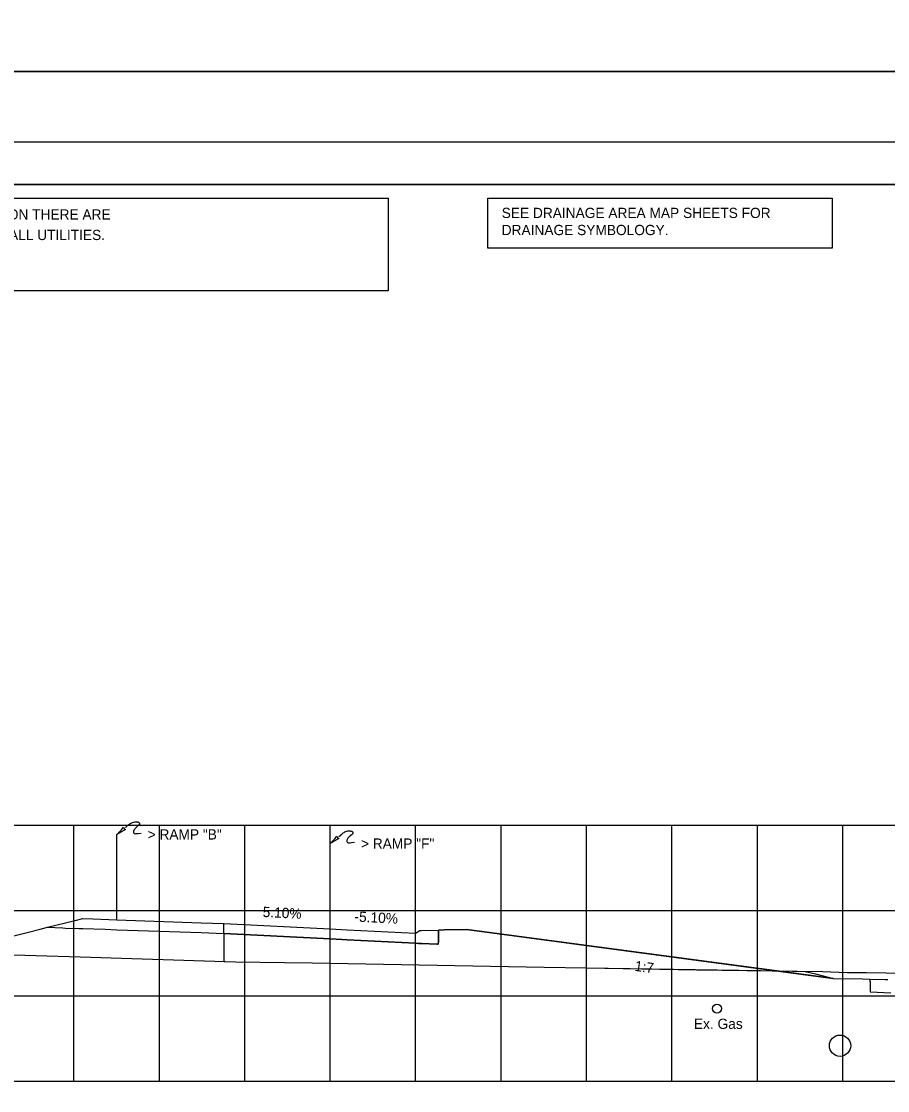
# Model space of a CAD drawing. Extents: x 2148105 to 2149976, y 144169 to 149705.
# Drawn here: x 2148377.2 to 2148478.6, y 144545.8 to 144671 of the extents above; entities that cross this region are included whole.
import ezdxf

# ---------------------------------------------------------------- set-up
doc = ezdxf.new("R2010")
doc.units = 0
for name, color, linetype in [('Bridge M-Header', 7, 'Continuous'), ('Default', 7, 'Continuous'), ('EX_Align', 7, 'Continuous'), ('INR_Tracking', 7, 'Continuous'), ('Ph1-PR-Ramp SF3 Rev-Curb', 7, 'Continuous'), ('PH1a-PR-DividingStrip', 7, 'Continuous'), ('PH1a-PR-ServRd', 7, 'Continuous'), ('PH2-PR-Barrier', 7, 'Continuous'), ('PR-ApproachSlab', 7, 'Continuous'), ('PR-Dividing Strip', 7, 'Continuous'), ('PR-SHLDR-RMP-H', 7, 'Continuous'), ('PR_Align_PI', 7, 'Continuous'), ('PR_Align_Ramp_E', 7, 'Continuous'), ('PR_Align_Ramp_J', 7, 'Continuous'), ('PR_Storm_Channel', 7, 'Continuous'), ('PR_Storm_Conc_Box_PH1B', 7, 'Continuous'), ('PR_Storm_Conc_Pipe', 7, 'Continuous'), ('PR_Storm_Conc_Pipe_PH1B', 7, 'Continuous'), ('PR_Storm_Inlet_CICI_PH1B', 7, 'Continuous'), ('PR_Storm_Junction_Box_PH1A', 7, 'Continuous'), ('PR_Storm_MH', 7, 'Continuous'), ('PR_Storm_Standard_Median_Drain_PH1B', 7, 'Continuous'), ('TopCut', 7, 'Continuous'), ('TOPO_BRIDGE_Pier Cap', 7, 'Continuous')]:
    doc.layers.add(name, color=color, linetype=linetype)

# ---------------------------------------------------------------- blocks, each defined once
blk = doc.blocks.new('POINT_DISPLAY')
at = {"layer": 'Default'}
blk.add_line((0, 0), (0, 0), dxfattribs=at)

msp = doc.modelspace()

# ---------------------------------------------------------------- linework, layer by layer
at = {"layer": 'EX_Align'}
msp.add_lwpolyline([(2148372.17, 144562.92), (2148377.99, 144564.37), (2148379.38, 144564.71), (2148380.24, 144564.93), (2148382.02, 144564.87), (2148382.35, 144564.85), (2148383.89, 144564.8), (2148384.35, 144564.79), (2148386.96, 144564.7), (2148388.36, 144564.65), (2148398.2, 144564.31), (2148400.86, 144564.22)], dxfattribs=at)
at = {"layer": 'INR_Tracking'}
msp.add_lwpolyline([(2148400.86, 144564.22), (2148413.32, 144563.58), (2148413.32, 144563.58), (2148414.66, 144563.51), (2148415.32, 144563.48), (2148415.32, 144563.48), (2148423.32, 144563.07), (2148423.66, 144563.05), (2148423.99, 144563.04), (2148425.84, 144562.94), (2148425.97, 144562.94), (2148425.98, 144563.27), (2148425.99, 144564.61), (2148426.69, 144564.62), (2148429.32, 144564.68), (2148472.18, 144558.95), (2148472.18, 144558.95)], dxfattribs=at)
at = {"layer": 'Ph1-PR-Ramp SF3 Rev-Curb'}
msp.add_circle((2148472.99, 144551.07), 1.25, dxfattribs=at)
at = {"layer": 'PH1a-PR-ServRd'}
msp.add_lwpolyline([(2148570.82, 144441.91), (2148255.82, 144441.91), (2148255.82, 144651.91), (2148570.82, 144651.91)], close=True, dxfattribs=at)
at = {"layer": 'PH2-PR-Barrier'}
msp.add_line((2148413.32, 144564.75), (2148413.32, 144574.75), dxfattribs=at)
for points in [[(2148413.32, 144574.75), (2148413.84, 144575.3), (2148414.1, 144575.6), (2148414.18, 144575.44), (2148414.32, 144575.32), (2148413.32, 144574.75)], [(2148414.33, 144575.56), (2148414.69, 144575.85), (2148414.85, 144575.98), (2148414.94, 144576.05), (2148415.04, 144576.11), (2148415.14, 144576.16), (2148415.26, 144576.19), (2148415.39, 144576.22), (2148415.49, 144576.23), (2148415.57, 144576.23), (2148415.65, 144576.23), (2148415.72, 144576.21), (2148415.78, 144576.2), (2148415.83, 144576.18), (2148415.87, 144576.15), (2148415.91, 144576.12), (2148415.95, 144576.08), (2148415.98, 144576.02), (2148415.97, 144575.96), (2148415.96, 144575.92), (2148415.91, 144575.85), (2148415.72, 144575.69), (2148415.53, 144575.53), (2148415.46, 144575.45), (2148415.39, 144575.38), (2148415.33, 144575.28), (2148415.29, 144575.22), (2148415.25, 144575.13), (2148415.25, 144575.05), (2148415.27, 144574.97), (2148415.31, 144574.9), (2148415.36, 144574.87), (2148415.42, 144574.84), (2148415.53, 144574.83), (2148415.66, 144574.83), (2148415.82, 144574.85), (2148416.15, 144574.89)]]:
    msp.add_lwpolyline(points, dxfattribs=at)
at = {"layer": 'PR-ApproachSlab'}
msp.add_lwpolyline([(2148468.9, 144559.77), (2148470.11, 144559.47), (2148472.18, 144558.95), (2148475.61, 144558.88), (2148476.47, 144558.86), (2148478.26, 144558.83), (2148478.51, 144558.82), (2148478.52, 144558.82), (2148478.52, 144558.82), (2148478.59, 144558.82)], dxfattribs=at)
at = {"layer": 'PR-Dividing Strip'}
msp.add_line((2148388.36, 144565.81), (2148388.36, 144575.81), dxfattribs=at)
for points in [[(2148389.37, 144576.63), (2148389.72, 144576.92), (2148389.88, 144577.05), (2148389.98, 144577.12), (2148390.08, 144577.18), (2148390.18, 144577.22), (2148390.29, 144577.26), (2148390.43, 144577.29), (2148390.52, 144577.3), (2148390.6, 144577.3), (2148390.69, 144577.29), (2148390.76, 144577.28), (2148390.81, 144577.26), (2148390.86, 144577.24), (2148390.91, 144577.22), (2148390.94, 144577.19), (2148390.98, 144577.14), (2148391.01, 144577.09), (2148391.01, 144577.03), (2148391, 144576.99), (2148390.94, 144576.92), (2148390.75, 144576.76), (2148390.57, 144576.59), (2148390.49, 144576.52), (2148390.43, 144576.44), (2148390.36, 144576.35), (2148390.33, 144576.29), (2148390.29, 144576.2), (2148390.28, 144576.12), (2148390.3, 144576.04), (2148390.35, 144575.97), (2148390.39, 144575.93), (2148390.45, 144575.91), (2148390.56, 144575.89), (2148390.7, 144575.9), (2148390.85, 144575.92), (2148391.19, 144575.95)], [(2148388.36, 144575.81), (2148388.87, 144576.36), (2148389.13, 144576.67), (2148389.22, 144576.5), (2148389.36, 144576.39), (2148388.36, 144575.81)]]:
    msp.add_lwpolyline(points, dxfattribs=at)
at = {"layer": 'PR-SHLDR-RMP-H'}
msp.add_lwpolyline([(2148468.9, 144559.77), (2148470.11, 144559.47), (2148472.18, 144558.95), (2148475.61, 144558.88), (2148476.47, 144558.86), (2148476.48, 144558.81), (2148476.48, 144558.53), (2148476.49, 144558.53), (2148476.5, 144558.53), (2148476.52, 144557.84), (2148476.52, 144557.7), (2148476.52, 144557.64), (2148476.53, 144557.37), (2148478.92, 144557.25)], dxfattribs=at)
at = {"layer": 'PR_Align_PI'}
msp.add_lwpolyline([(2148380.24, 144564.93), (2148383.48, 144565.73), (2148384.36, 144565.95), (2148385.53, 144565.91), (2148388.36, 144565.81), (2148398.21, 144565.47), (2148400.86, 144565.38)], dxfattribs=at)
at = {"layer": 'PR_Align_Ramp_E'}
for points in [[(2148219.95, 144905.16), (2148579.95, 144905.16), (2148579.95, 144665.16), (2148219.95, 144665.16)], [(2148219.95, 144665.16), (2148579.95, 144665.16), (2148579.95, 144425.16), (2148219.95, 144425.16)]]:
    msp.add_lwpolyline(points, close=True, dxfattribs=at)
at = {"layer": 'PR_Align_Ramp_J'}
msp.add_lwpolyline([(2148236.32, 144656.91), (2148576.32, 144656.91), (2148576.32, 144436.91), (2148236.32, 144436.91)], close=True, dxfattribs=at)
at = {"layer": 'PR_Storm_Channel'}
msp.add_lwpolyline([(2148400.86, 144565.38), (2148413.32, 144564.75), (2148415.32, 144564.65), (2148423.32, 144564.24), (2148423.82, 144564.57), (2148423.99, 144564.57), (2148425.99, 144564.61)], dxfattribs=at)
at = {"layer": 'PR_Storm_Conc_Box_PH1B'}
for p, q in [((2148263.32, 144576.91), (2148563.32, 144576.91)), ((2148383.32, 144546.91), (2148383.32, 144576.91)), ((2148393.32, 144546.91), (2148393.32, 144576.91)), ((2148403.32, 144546.91), (2148403.32, 144576.91)), ((2148413.32, 144546.91), (2148413.32, 144576.91)), ((2148423.32, 144546.91), (2148423.32, 144576.91)), ((2148433.32, 144546.91), (2148433.32, 144576.91)), ((2148443.32, 144546.91), (2148443.32, 144576.91)), ((2148453.32, 144546.91), (2148453.32, 144576.91)), ((2148463.32, 144546.91), (2148463.32, 144576.91)), ((2148473.32, 144546.91), (2148473.32, 144576.91)), ((2148263.32, 144566.91), (2148563.32, 144566.91)), ((2148263.32, 144556.91), (2148563.32, 144556.91)), ((2148263.32, 144546.91), (2148563.32, 144546.91))]:
    msp.add_line(p, q, dxfattribs=at)
at = {"layer": 'PR_Storm_Conc_Pipe'}
msp.add_lwpolyline([(2148400.86, 144564.22), (2148400.86, 144564.55), (2148400.86, 144565.38)], dxfattribs=at)
at = {"layer": 'PR_Storm_Conc_Pipe_PH1B'}
msp.add_lwpolyline([(2148255.82, 144441.91), (2148570.82, 144441.91), (2148570.82, 144651.91), (2148255.82, 144651.91)], close=True, dxfattribs=at)
msp.add_lwpolyline([(2148255.82, 144441.91), (2148570.82, 144441.91), (2148570.82, 144651.91), (2148255.82, 144651.91)], close=True, dxfattribs=at)
at = {"layer": 'PR_Storm_Inlet_CICI_PH1B'}
msp.add_lwpolyline([(2148368.44, 144561.95), (2148384.04, 144561.46), (2148402.22, 144560.89), (2148407.95, 144560.81), (2148411.2, 144560.77), (2148438.38, 144560.26), (2148443.32, 144560.18), (2148456.19, 144559.96), (2148470.92, 144559.74), (2148473.87, 144559.64), (2148476.08, 144559.63), (2148489.88, 144559.4), (2148515.32, 144558.7), (2148520.36, 144558.53), (2148525.1, 144558.54), (2148532.95, 144558.49), (2148540.34, 144558.33), (2148543.94, 144558.29), (2148547.3, 144558.23), (2148563.32, 144557.9)], dxfattribs=at)
at = {"layer": 'PR_Storm_Junction_Box_PH1A'}
msp.add_circle((2148458.59, 144555.41), 0.516, dxfattribs=at)
at = {"layer": 'PR_Storm_MH'}
for points in [[(2148257.69, 144650.34), (2148420.12, 144650.34), (2148420.12, 144639.47), (2148257.69, 144639.47)], [(2148431.78, 144650.34), (2148472.07, 144650.34), (2148472.07, 144644.47), (2148431.78, 144644.47)]]:
    msp.add_lwpolyline(points, close=True, dxfattribs=at)
at = {"layer": 'PR_Storm_Standard_Median_Drain_PH1B'}
msp.add_line((2148263.32, 144546.91), (2148563.32, 144546.91), dxfattribs=at)
at = {"layer": 'TopCut'}
msp.add_lwpolyline([(2148400.86, 144564.22), (2148400.86, 144560.94), (2148402.22, 144560.89), (2148407.95, 144560.81), (2148411.2, 144560.77), (2148438.38, 144560.26), (2148443.32, 144560.18), (2148461.16, 144559.9), (2148462.26, 144559.89), (2148462.3, 144559.89), (2148463.68, 144559.86), (2148465.36, 144559.83), (2148465.61, 144559.83), (2148429.32, 144564.68), (2148426.69, 144564.62), (2148425.99, 144564.61), (2148425.98, 144563.27), (2148425.97, 144562.94), (2148425.84, 144562.94), (2148423.99, 144563.04), (2148423.66, 144563.05), (2148423.32, 144563.07), (2148415.32, 144563.48), (2148415.32, 144563.48), (2148414.66, 144563.51), (2148413.32, 144563.58), (2148413.32, 144563.58)], close=True, dxfattribs=at)
at = {"layer": 'TOPO_BRIDGE_Pier Cap'}
msp.add_lwpolyline([(2148465.61, 144559.83), (2148467.42, 144559.8), (2148468.9, 144559.77), (2148470.11, 144559.47), (2148472.18, 144558.95)], close=True, dxfattribs=at)

# ---------------------------------------------------------------- block references
at = {"layer": 'PR_Storm_Conc_Pipe_PH1B', "xscale": 10, "yscale": 10}
for p in [(2148400.86, 144565.38), (2148400.86, 144565.38), (2148415.32, 144564.65), (2148415.32, 144564.65), (2148423.32, 144564.24), (2148423.32, 144564.24)]:
    msp.add_blockref('POINT_DISPLAY', p, dxfattribs=at)

# ---------------------------------------------------------------- texts
at = {"layer": 'Bridge M-Header'}
for s, p in [('5.10%', (2148405.39, 144566.15)), ('-5.10%', (2148416.14, 144565.61))]:
    msp.add_text(s, height=1.2, rotation=357.0804, dxfattribs=at).set_placement(p)
at = {"layer": 'PH1a-PR-DividingStrip'}
msp.add_text('1:7', height=1.2, rotation=352.3877, dxfattribs=at).set_placement((2148448.9, 144559.84))
at = {"layer": 'PH2-PR-Barrier'}
msp.add_text('> RAMP "F"', height=1.2, rotation=360, dxfattribs=at).set_placement((2148416.92, 144574.14))
at = {"layer": 'PR-Dividing Strip'}
msp.add_text('> RAMP "B"', height=1.2, rotation=360, dxfattribs=at).set_placement((2148391.95, 144575.21))
at = {"layer": 'PR_Storm_Junction_Box_PH1A'}
msp.add_text('Ex. Gas', height=1.2, rotation=360, dxfattribs=at).set_placement((2148455.89, 144553.03))
at = {"layer": 'PR_Storm_MH'}
for s, p in [("(CAUTION) THE LOCATION OF ALL UTILITIES AS SHOWN ARE APPROXIMATE. DUE TO RELOCATION'S PLANNED OR PRESENTLY UNDER CONSTRUCTION THERE ARE ", (2148258.92, 144647.82)), ('SEE DRAINAGE AREA MAP SHEETS FOR', (2148433.39, 144648)), ('DRAINAGE SYMBOLOGY.', (2148433.39, 144646)), ('SOME UTILITIES THAT WILL BE RELOCATED AND NOT SHOWN ON THESE PLANS. THE CONTRACTOR SHALL BE RESPONSIBLE FOR ANY DAMAGE TO ALL UTILITIES.', (2148258.92, 144645.42))]:
    msp.add_text(s, height=1.2, dxfattribs=at).set_placement(p)

doc.saveas('drawing.dxf')
